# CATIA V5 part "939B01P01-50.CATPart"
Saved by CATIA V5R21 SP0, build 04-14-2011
Part number: 939B01P01-50
Bounding box of the stored display mesh (mm): x -17.1 to 17.1, y -76.2 to 76.2, z -4.4 to 45.6
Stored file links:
  C:\Users\ALI OZGUN\Desktop\alhan\TESLIMEDILEN3\939B01P01-50.CATPart
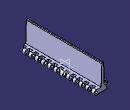
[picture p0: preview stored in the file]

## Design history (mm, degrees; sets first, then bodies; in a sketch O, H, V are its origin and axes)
Body1 (main body)
  Sketch1 on zx-plane, origin (0, 0, 0), H (-1, 0, 0), V (0, 0, 1)
    construction line L1 (-12.7, 0) -> (12.7, 0)
    point P1 (-12.7, 0)
    line L2 (-12.7, 4.4) -> (12.7, 4.4)
    line L3 (12.7, -4.4) -> (-12.7, -4.4)
    arc A1 centre (12.7, 0) radius 4.4 from (12.7, 4.4) to (12.7, -4.4) cw
    arc A2 centre (-12.7, 0) radius 4.4 from (-12.7, -4.4) to (-12.7, 4.4) cw
    distance L1 L2 = 4.4
    length L1 = 25.4
    distance P1 V = 12.7
    coincidence: P1 H
    horizontal: L1 H
    tangency: A1 L2, A2 L2, A1 L3, A2 L3
  Pad1: profile Sketch1, direction (0, 1, 0), length 76.2, mirrored extent
  Sketch2 on face of Pad1 from Sketch1.L2, origin (0, 0, 4.4), H (1, 0, 0), V (0, 1, 0)
    line L1 (-22.3127, -63.5) -> (-9.75, -63.5)
    line L2 (-9.75, -63.5) -> (-9.75, -70.6)
    line L3 (-9.75, -70.6) -> (-22.3127, -70.6)
    line L4 (-22.3127, -70.6) -> (-22.3127, -63.5)
    line L5 (24.6678, -76.95) -> (9.75, -76.95)
    line L6 (9.75, -76.95) -> (9.75, -69.85)
    line L7 (9.75, -69.85) -> (24.6678, -69.85)
    line L8 (24.6678, -69.85) -> (24.6678, -76.95)
    reference projected line E1 (-12.7, -76.2) -> (12.7, -76.2) from edge [start face of Pad1 | face of Pad1 from Sketch1.L2]
    reference projected line E2 (-12.7, -76.2) -> (12.7, -76.2) from edge [start face of Pad1 | face of Pad1 from Sketch1.L2]
    distance L3 E1 = 5.6
    length L4 = 7.1
    distance L7 L5 = 7.1
    distance L5 E2 = 0.75
    distance L2 L6 = 19.5
    distance L2 V = 9.75
    horizontal: L1 H, L3 H, L5 H, L7 H
    vertical: L2 V, L4 V, L6 V, L8 V
  Pocket1: profile Sketch2, direction (0, 0, -1), length 76.2
  RectPattern1: of Pocket1, direction 1 instances 12, spacing 12.7, along axis of face of Pad1 from Sketch1.A2
  Sketch3 on face of Pad1 from Sketch1.L3, origin (0, 0, -4.4), H (1, 0, 0), V (0, -1, 0)
    line L1 (-6.5, -54.6) -> (6.5, -54.6)
    line L2 (6.5, -54.6) -> (6.5, -73.7)
    line L3 (6.5, -73.7) -> (-6.5, -73.7)
    line L4 (-6.5, -73.7) -> (-6.5, -54.6)
    construction line L5 (-4.5, -51.1) -> (4.5, -51.1)
    point P5 (-4.5, -51.1)
    line L6 (-4.5, -49.6) -> (4.5, -49.6)
    line L7 (4.5, -52.6) -> (-4.5, -52.6)
    arc A1 centre (4.5, -51.1) radius 1.5 from (4.5, -49.6) to (4.5, -52.6) cw
    arc A2 centre (-4.5, -51.1) radius 1.5 from (-4.5, -52.6) to (-4.5, -49.6) cw
    reference projected line E1 (12.7, -76.2) -> (-12.7, -76.2) from edge [face of Pad1 from Sketch1.L3 | end face of Pad1]
    distance L5 L6 = 1.5
    distance L1 L3 = 19.1
    distance L4 L2 = 13
    distance L4 V = 6.5
    distance E1 L3 = 2.5
    distance P5 V = 4.5
    length L5 = 9
    distance L7 L1 = 2
    horizontal: L1 H, L3 H, L5 H
    vertical: L2 V, L4 V
    tangency: A1 L6, A2 L6, A1 L7, A2 L7
  Pocket2: profile Sketch3, direction (0, 0, 1), length 6
  RectPattern2: of Pocket2, direction 1 instances 6, spacing 25.8, along axis of face of Pad1 from Sketch1.A2 reversed
  Sketch4 on zx-plane, origin (0, 0, 0), H (-1, 0, 0), V (0, 0, 1)
    circle A1 centre (12.7, 0) radius 2.3
    point P1 (12.7, 0)
    circle A2 centre (-12.7, 0) radius 2.3
    point P2 (-12.7, 0)
    reference projected arc E1 centre (12.7, 0) radius 4.4 from (12.7, -4.4) to (12.7, 4.4) ccw from edge [face of RectPattern1 | face of Pad1 from Sketch1.A1]
    reference projected arc E2 centre (-12.7, 0) radius 4.4 from (-12.7, 4.4) to (-12.7, -4.4) ccw from edge [face of Pad1 from Sketch1.A2 | end face of Pad1]
    radius A1 = 2.3
    radius A2 = 2.3
    coincidence: P1 H, P2 H
    concentricity: P1 E1, A2 E2
  Pocket3: profile Sketch4, direction (0, -1, 0), length 97.8, mirrored extent
  Body2
    Solid1: linked copy from another document
    Symmetry1: Reference yz-plane, ToTransfor Solid1
    Translate1: Direction edge [face of Pocket1 from Sketch2.L2 | face of Pad1 from Sketch1.L3], Length 6.35, ToTransfor Symmetry1
    Body3
      Sketch5 on face of RectPattern1, origin (9.75, 0, 0), H (0, 1, 0), V (0, 0, 1)
      Pad2: profile Sketch5, direction (1, 0, 0), length 12
      Sketch6 on face of Pad2, origin (0, 69.85, 0), H (-1, 0, 0), V (0, 0, 1)
        point P2 (-21.75, 4.4)
        arc A1 centre (-16.4898, 1.5645) radius 9 from (-9.75, -4.4) to (-7.9481, 4.4) ccw
        point P8 (-21.75, 4.4)
        construction line L1 (-9.75, 4.4) -> (-21.75, 4.4)
        line L2 (-7.9481, 4.4) -> (-21.75, 4.4)
        line L3 (-9.75, -4.4) -> (-21.75, -4.4)
        line L4 (-21.75, -4.4) -> (-21.75, 4.4)
        radius A1 = 9
        coincidence: P2 P8
      Pad3: profile Sketch6, direction (0, 1, 0), up to face of Pad2
      RectPattern3: of the body so far, direction 1 instances 12, spacing 12.7, along edge [face of Pad3 | face of Pad3] reversed
    Add1: tool Body3
  Remove1: tool Body2
  Sketch7 on zx-plane, origin (0, 0, 0), H (-1, 0, 0), V (0, 0, 1)
    projected line E1 (7.9481, 4.4) -> (-12.7, 4.4) from edge [face of Pad1 from Sketch1.L2 | end face of Pad1]
    projected line E2 (3.2, 4.4) -> (-3.2, 4.4) from edge [face of Pad1 from Sketch1.L2 | end face of Pad1]
    point P3 (-3.2, 4.4)
    line L1 (-3.2, 4.4) -> (-2, 45.6)
    point P4 (-2, 45.6)
    line L2 (-2, 45.6) -> (2, 45.6)
    line L3 (2, 45.6) -> (3.2, 4.4)
    reference projected line E3 (-12.7, -4.4) -> (12.7, -4.4) from edge [face of Pad1 from Sketch1.L3 | end face of Pad1]
    distance L2 E3 = 50
    distance P3 V = 3.2
    distance P4 V = 2
    coincidence: P3 E1, P3 L1
    horizontal: L2 H
    symmetry: L1 L3 V
  Pad4: profile Sketch7, direction (0, 1, 0), length 76.2, mirrored extent
  Fillet1: radius 1, on edge [face of Pad4 from Sketch7.L2 | face of Pad4 from Sketch7.L3]; edge [face of Pad4 from Sketch7.L1 | face of Pad4 from Sketch7.L2]
Body4
  Solid2: linked copy from another document
  Translate2: Direction yz-plane, Length 25.4, ToTransfor Solid2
